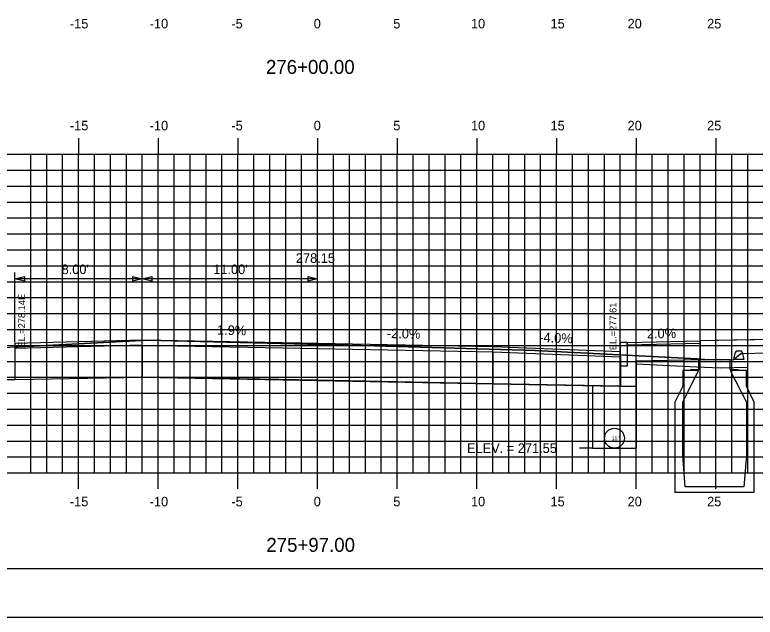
# Model space of a CAD drawing. Extents: x 853785 to 853955, y 366268 to 366378.
# Drawn here: x 853849.44 to 853895.9, y 366268.18 to 366305.99 of the extents above; entities that cross this region are included whole.
import ezdxf

# ---------------------------------------------------------------- set-up
doc = ezdxf.new("R2010")
doc.units = 0
for name, color, linetype in [('ANNOTATION', 7, 'Continuous'), ('BORDER', 7, 'Continuous'), ('D_Curb_Type_1_Rt', 7, 'Continuous'), ('D_Roadway_Centerline_Text', 7, 'Continuous'), ('D_Roadway_Edge_Shoulder', 7, 'Continuous'), ('D_Roadway_FinishedGrade', 7, 'Continuous'), ('D_Roadway_Sidewalks_Paved', 7, 'Continuous'), ('D_Roadway_SubGrade', 7, 'Continuous'), ('D_Text_Standard', 7, 'Continuous'), ('DIMENSIONS', 7, 'Continuous'), ('H_V ANNOTATION', 7, 'Continuous'), ('JUNK COM EXC', 7, 'Continuous'), ('JUNK FILL', 7, 'Continuous'), ('junk strct exc', 7, 'Continuous'), ('MAJOR', 7, 'Continuous'), ('MINOR', 7, 'Continuous'), ('PDRAIN', 7, 'Continuous'), ('PLOT BOUNDARY', 7, 'Continuous'), ('S_Curb_Type_3', 7, 'Continuous'), ('S_Drainage_CB', 7, 'Continuous'), ('S_Roadway_Centerline', 7, 'Continuous')]:
    doc.layers.add(name, color=color, linetype=linetype)

msp = doc.modelspace()

# ---------------------------------------------------------------- linework, layer by layer
at = {"layer": 'BORDER'}
msp.add_line((853793.435, 366271.236), (853953.435, 366271.236), dxfattribs=at)
at = {"layer": 'D_Curb_Type_1_Rt'}
msp.add_lwpolyline([(853887.855, 366285.431), (853887.855, 366283.931), (853887.438, 366283.931), (853887.438, 366285.431)], close=True, dxfattribs=at)
at = {"layer": 'D_Roadway_Edge_Shoulder'}
msp.add_line((853849.435, 366285.374), (853849.439, 366285.041), dxfattribs=at)
msp.add_lwpolyline([(853849.435, 366285.374), (853857.441, 366285.585), (853868.438, 366285.387), (853879.438, 366285.167), (853887.438, 366284.847)], dxfattribs=at)
at = {"layer": 'D_Roadway_FinishedGrade'}
msp.add_line((853907.158, 366285.817), (853892.443, 366285.522), dxfattribs=at)
at = {"layer": 'D_Roadway_Sidewalks_Paved'}
msp.add_lwpolyline([(853887.855, 366285.43), (853892.443, 366285.522), (853892.443, 366285.355), (853887.855, 366285.263)], close=True, dxfattribs=at)
at = {"layer": 'D_Roadway_SubGrade'}
msp.add_line((853824.435, 366283.424), (853849.444, 366283.092), dxfattribs=at)
for points in [[(853857.444, 366285.252), (853849.439, 366285.041), (853849.444, 366283.092), (853857.444, 366283.252)], [(853857.444, 366283.252), (853857.444, 366285.252), (853868.444, 366285.054), (853879.444, 366284.834), (853879.444, 366282.834), (853868.444, 366283.054)], [(853879.444, 366284.834), (853887.444, 366284.514), (853887.444, 366282.674), (853879.444, 366282.834)]]:
    msp.add_lwpolyline(points, close=True, dxfattribs=at)
for points in [[(853887.442, 366282.674), (853888.442, 366282.654), (853888.442, 366284.276), (853892.444, 366284.355), (853892.444, 366285.355)], [(853888.442, 366284.088), (853892.231, 366283.886), (853893.7, 366283.834), (853895.435, 366283.872)]]:
    msp.add_lwpolyline(points, dxfattribs=at)
at = {"layer": 'D_Text_Standard'}
msp.add_lwpolyline([(853885.692, 366278.786), (853885.543, 366278.786), (853884.863, 366278.786)], dxfattribs=at)
at = {"layer": 'DIMENSIONS'}
for p, q in [((853849.438, 366285.45), (853849.438, 366289.815)), ((853857.438, 366285.77), (853857.438, 366289.815)), ((853868.438, 366285.587), (853868.438, 366289.815)), ((853857.438, 366289.415), (853849.438, 366289.415)), ((853868.438, 366289.415), (853857.438, 366289.415)), ((853895.435, 366283.872), (853895.435, 366284.741))]:
    msp.add_line(p, q, dxfattribs=at)
for points in [[(853850.038, 366289.265), (853849.438, 366289.415), (853850.038, 366289.565)], [(853856.838, 366289.565), (853857.438, 366289.415), (853856.838, 366289.265)], [(853858.038, 366289.265), (853857.438, 366289.415), (853858.038, 366289.565)], [(853867.838, 366289.565), (853868.438, 366289.415), (853867.838, 366289.265)]]:
    msp.add_lwpolyline(points, close=True, dxfattribs=at)
at = {"layer": 'JUNK COM EXC'}
msp.add_lwpolyline([(853849.441, 366285.147), (853849.444, 366283.092), (853857.444, 366283.252), (853879.444, 366282.834), (853888.442, 366282.654), (853888.442, 366284.276), (853892.444, 366284.355), (853892.444, 366284.379), (853892.253, 366284.386), (853882.091, 366284.926), (853871.998, 366285.204), (853868.661, 366285.302), (853862.721, 366285.439), (853857.775, 366285.567), (853850.621, 366285.197), (853849.441, 366285.147)], dxfattribs=at)
at = {"layer": 'JUNK FILL'}
msp.add_lwpolyline([(853892.435, 366285.522), (853892.435, 366285.355), (853892.444, 366285.355), (853892.444, 366284.379), (853892.445, 366284.379), (853893.703, 366284.334), (853894.544, 366284.353), (853894.991, 366284.732), (853895.13, 366284.733), (853902.757, 366284.942), (853904.091, 366285.128), (853907.158, 366285.817), (853899.801, 366285.67), (853892.443, 366285.522)], close=True, dxfattribs=at)
at = {"layer": 'junk strct exc'}
msp.add_lwpolyline([(853885.692, 366282.709), (853885.692, 366278.786), (853888.442, 366278.786), (853888.442, 366282.654)], close=True, dxfattribs=at)
at = {"layer": 'MAJOR'}
for p, q in [((853853.435, 366298.238), (853853.435, 366297.236)), ((853858.435, 366298.238), (853858.435, 366297.236)), ((853863.435, 366298.238), (853863.435, 366297.236)), ((853868.435, 366298.238), (853868.435, 366297.236)), ((853873.435, 366298.238), (853873.435, 366297.236)), ((853878.435, 366298.238), (853878.435, 366297.236)), ((853883.435, 366298.238), (853883.435, 366297.236)), ((853888.435, 366298.238), (853888.435, 366297.236)), ((853893.435, 366298.238), (853893.435, 366297.236)), ((853798.435, 366297.236), (853938.435, 366297.236)), ((853798.435, 366297.236), (853938.435, 366297.236)), ((853853.435, 366277.236), (853853.435, 366297.236)), ((853858.435, 366277.236), (853858.435, 366297.236)), ((853863.435, 366277.236), (853863.435, 366297.236)), ((853868.435, 366277.236), (853868.435, 366297.236)), ((853873.435, 366277.236), (853873.435, 366297.236)), ((853878.435, 366277.236), (853878.435, 366297.236)), ((853883.435, 366277.236), (853883.435, 366297.236)), ((853888.435, 366277.236), (853888.435, 366297.236)), ((853893.435, 366277.236), (853893.435, 366297.236)), ((853798.435, 366292.236), (853938.435, 366292.236)), ((853798.435, 366287.236), (853938.435, 366287.236)), ((853798.435, 366282.236), (853938.435, 366282.236)), ((853798.435, 366277.236), (853938.435, 366277.236)), ((853798.435, 366277.236), (853938.435, 366277.236)), ((853853.435, 366276.234), (853853.435, 366277.236)), ((853858.435, 366276.234), (853858.435, 366277.236)), ((853863.435, 366276.234), (853863.435, 366277.236)), ((853868.435, 366276.234), (853868.435, 366277.236)), ((853873.435, 366276.234), (853873.435, 366277.236)), ((853878.435, 366276.234), (853878.435, 366277.236)), ((853883.435, 366276.234), (853883.435, 366277.236)), ((853888.435, 366276.234), (853888.435, 366277.236)), ((853893.435, 366276.234), (853893.435, 366277.236))]:
    msp.add_line(p, q, dxfattribs=at)
at = {"layer": 'MINOR'}
for p, q in [((853850.435, 366277.236), (853850.435, 366297.236)), ((853851.435, 366277.236), (853851.435, 366297.236)), ((853852.435, 366277.236), (853852.435, 366297.236)), ((853854.435, 366277.236), (853854.435, 366297.236)), ((853855.435, 366277.236), (853855.435, 366297.236)), ((853856.435, 366277.236), (853856.435, 366297.236)), ((853857.435, 366277.236), (853857.435, 366297.236)), ((853859.435, 366277.236), (853859.435, 366297.236)), ((853860.435, 366277.236), (853860.435, 366297.236)), ((853861.435, 366277.236), (853861.435, 366297.236)), ((853862.435, 366277.236), (853862.435, 366297.236)), ((853864.435, 366277.236), (853864.435, 366297.236)), ((853865.435, 366277.236), (853865.435, 366297.236)), ((853866.435, 366277.236), (853866.435, 366297.236)), ((853867.435, 366277.236), (853867.435, 366297.236)), ((853869.435, 366277.236), (853869.435, 366297.236)), ((853870.435, 366277.236), (853870.435, 366297.236)), ((853871.435, 366277.236), (853871.435, 366297.236)), ((853872.435, 366277.236), (853872.435, 366297.236)), ((853874.435, 366277.236), (853874.435, 366297.236)), ((853875.435, 366277.236), (853875.435, 366297.236)), ((853876.435, 366277.236), (853876.435, 366297.236)), ((853877.435, 366277.236), (853877.435, 366297.236)), ((853879.435, 366277.236), (853879.435, 366297.236)), ((853880.435, 366277.236), (853880.435, 366297.236)), ((853881.435, 366277.236), (853881.435, 366297.236)), ((853882.435, 366277.236), (853882.435, 366297.236)), ((853884.435, 366277.236), (853884.435, 366297.236)), ((853885.435, 366277.236), (853885.435, 366297.236)), ((853886.435, 366277.236), (853886.435, 366297.236)), ((853887.435, 366277.236), (853887.435, 366297.236)), ((853889.435, 366277.236), (853889.435, 366297.236)), ((853890.435, 366277.236), (853890.435, 366297.236)), ((853891.435, 366277.236), (853891.435, 366297.236)), ((853892.435, 366277.236), (853892.435, 366297.236)), ((853894.435, 366277.236), (853894.435, 366297.236)), ((853895.435, 366277.236), (853895.435, 366297.236)), ((853798.435, 366296.236), (853938.435, 366296.236)), ((853798.435, 366295.236), (853938.435, 366295.236)), ((853798.435, 366294.236), (853938.435, 366294.236)), ((853798.435, 366293.236), (853938.435, 366293.236)), ((853798.435, 366291.236), (853938.435, 366291.236)), ((853798.435, 366290.236), (853938.435, 366290.236)), ((853798.435, 366289.236), (853938.435, 366289.236)), ((853798.435, 366288.236), (853938.435, 366288.236)), ((853798.435, 366286.236), (853938.435, 366286.236)), ((853798.435, 366285.236), (853938.435, 366285.236)), ((853798.435, 366284.236), (853938.435, 366284.236)), ((853798.435, 366283.236), (853938.435, 366283.236)), ((853798.435, 366281.236), (853938.435, 366281.236)), ((853798.435, 366280.236), (853938.435, 366280.236)), ((853798.435, 366279.236), (853938.435, 366279.236)), ((853798.435, 366278.236), (853938.435, 366278.236))]:
    msp.add_line(p, q, dxfattribs=at)
at = {"layer": 'PDRAIN'}
msp.add_lwpolyline([(853885.692, 366282.709), (853885.692, 366278.786), (853888.442, 366278.786), (853888.442, 366282.654)], dxfattribs=at)
msp.add_circle((853887.067, 366279.411), 0.625, dxfattribs=at)
at = {"layer": 'PLOT BOUNDARY'}
msp.add_lwpolyline([(853785.342, 366268.177), (853955.342, 366268.177), (853955.342, 366378.177), (853785.342, 366378.177)], close=True, dxfattribs=at)
at = {"layer": 'S_Curb_Type_3'}
for points in [[(853895.074, 366284.805), (853895.176, 366284.361), (853894.551, 366284.361), (853894.654, 366284.805)], [(853894.776, 366284.902), (853894.952, 366284.902)]]:
    msp.add_lwpolyline(points, dxfattribs=at)
for centre, start, end in [((853894.776, 366284.777), 90, 167.0054), ((853894.952, 366284.777), 12.9946, 90)]:
    msp.add_arc(centre, 0.125, start, end, dxfattribs=at)
at = {"layer": 'S_Drainage_CB'}
for p, q in [((853892.333, 366283.671), (853891.349, 366283.671)), ((853891.349, 366283.671), (853891.349, 366282.686)), ((853891.349, 366281.669), (853892.333, 366283.671)), ((853895.352, 366283.671), (853894.335, 366283.671)), ((853894.335, 366283.671), (853895.352, 366281.669)), ((853895.352, 366282.686), (853895.352, 366283.671)), ((853891.349, 366282.686), (853890.857, 366281.669)), ((853895.844, 366281.669), (853895.352, 366282.686)), ((853890.857, 366281.669), (853890.857, 366276.026)), ((853891.349, 366278.356), (853891.349, 366281.669)), ((853895.352, 366281.669), (853895.352, 366278.356)), ((853895.844, 366276.026), (853895.844, 366281.669)), ((853891.513, 366276.354), (853891.349, 366278.356)), ((853895.352, 366278.356), (853895.188, 366276.354)), ((853895.188, 366276.354), (853891.513, 366276.354)), ((853890.857, 366276.026), (853895.844, 366276.026))]:
    msp.add_line(p, q, dxfattribs=at)
msp.add_lwpolyline([(853894.827, 366283.712), (853894.335, 366283.712), (853894.335, 366284.336), (853892.333, 366284.336), (853892.333, 366283.712), (853891.841, 366283.712)], dxfattribs=at)
at = {"layer": 'S_Roadway_Centerline'}
msp.add_lwpolyline([(853837.576, 366284.644), (853850.621, 366285.197), (853857.775, 366285.567), (853862.721, 366285.439), (853868.661, 366285.302), (853871.998, 366285.204), (853882.091, 366284.926), (853892.253, 366284.386), (853893.703, 366284.334), (853894.544, 366284.353), (853894.551, 366284.361), (853894.991, 366284.732), (853895.13, 366284.733), (853902.757, 366284.942), (853904.091, 366285.128), (853909.786, 366286.408), (853911.32, 366286.334), (853918.965, 366286.226), (853919.002, 366286.986), (853919.212, 366288.09)], dxfattribs=at)

# ---------------------------------------------------------------- texts
at = {"layer": 'ANNOTATION'}
for s, rotation, p in [('1.9%', 358.8886, (853862.123, 366285.91)), ('-2.0%', 358.8542, (853872.781, 366285.7)), ('-4.0%', 357.7095, (853882.337, 366285.452)), ('2.0%', 1.1488, (853889.108, 366285.672))]:
    msp.add_text(s, height=0.6, rotation=rotation, dxfattribs=at).set_placement(p)
at = {"layer": 'D_Roadway_Centerline_Text'}
msp.add_text('278.15', height=0.6, dxfattribs=at).set_placement((853867.073, 366290.419))
at = {"layer": 'D_Text_Standard'}
for s, p in [(' EL.=278.14È', (853850.082, 366284.941)), (' EL.=277.61', (853887.193, 366284.778))]:
    msp.add_text(s, height=0.4335, rotation=90, dxfattribs=at).set_placement(p)
msp.add_text('ELEV. = 271.55', height=0.6, dxfattribs=at).set_placement((853877.811, 366278.486))
at = {"layer": 'DIMENSIONS'}
for s, p in [("8.00'", (853852.371, 366289.715)), ("11.00'", (853861.887, 366289.715))]:
    msp.add_text(s, height=0.6, dxfattribs=at).set_placement(p)
at = {"layer": 'H_V ANNOTATION'}
for s, height, p in [('-15', 0.6, (853852.892, 366305.136)), ('-10', 0.6, (853857.9, 366305.136)), ('-5', 0.6, (853863.026, 366305.136)), ('0', 0.6, (853868.194, 366305.136)), ('5', 0.6, (853873.186, 366305.136)), ('10', 0.6, (853878.061, 366305.136)), ('15', 0.6, (853883.053, 366305.136)), ('20', 0.6, (853887.889, 366305.136)), ('25', 0.6, (853892.881, 366305.136)), ('276+00.00', 0.875, (853865.197, 366302.28)), ('-15', 0.6, (853852.892, 366298.736)), ('-10', 0.6, (853857.9, 366298.736)), ('-5', 0.6, (853863.026, 366298.736)), ('0', 0.6, (853868.194, 366298.736)), ('5', 0.6, (853873.186, 366298.736)), ('10', 0.6, (853878.061, 366298.736)), ('15', 0.6, (853883.053, 366298.736)), ('20', 0.6, (853887.889, 366298.736)), ('25', 0.6, (853892.881, 366298.736)), ('-15', 0.6, (853852.892, 366275.136)), ('-10', 0.6, (853857.9, 366275.136)), ('-5', 0.6, (853863.026, 366275.136)), ('0', 0.6, (853868.194, 366275.136)), ('5', 0.6, (853873.186, 366275.136)), ('10', 0.6, (853878.061, 366275.136)), ('15', 0.6, (853883.053, 366275.136)), ('20', 0.6, (853887.889, 366275.136)), ('25', 0.6, (853892.881, 366275.136)), ('275+97.00', 0.875, (853865.22, 366272.28))]:
    msp.add_text(s, height=height, dxfattribs=at).set_placement(p)
at = {"layer": 'PDRAIN'}
msp.add_text('15"', height=0.25, dxfattribs=at).set_placement((853886.88, 366279.286))
at = {"layer": 'S_Roadway_Centerline'}
for s, p in [('C', (853868.655, 366285.302)), ('L', (853868.661, 366285.294))]:
    msp.add_text(s, height=0.0146, dxfattribs=at).set_placement(p)

doc.saveas('drawing.dxf')
